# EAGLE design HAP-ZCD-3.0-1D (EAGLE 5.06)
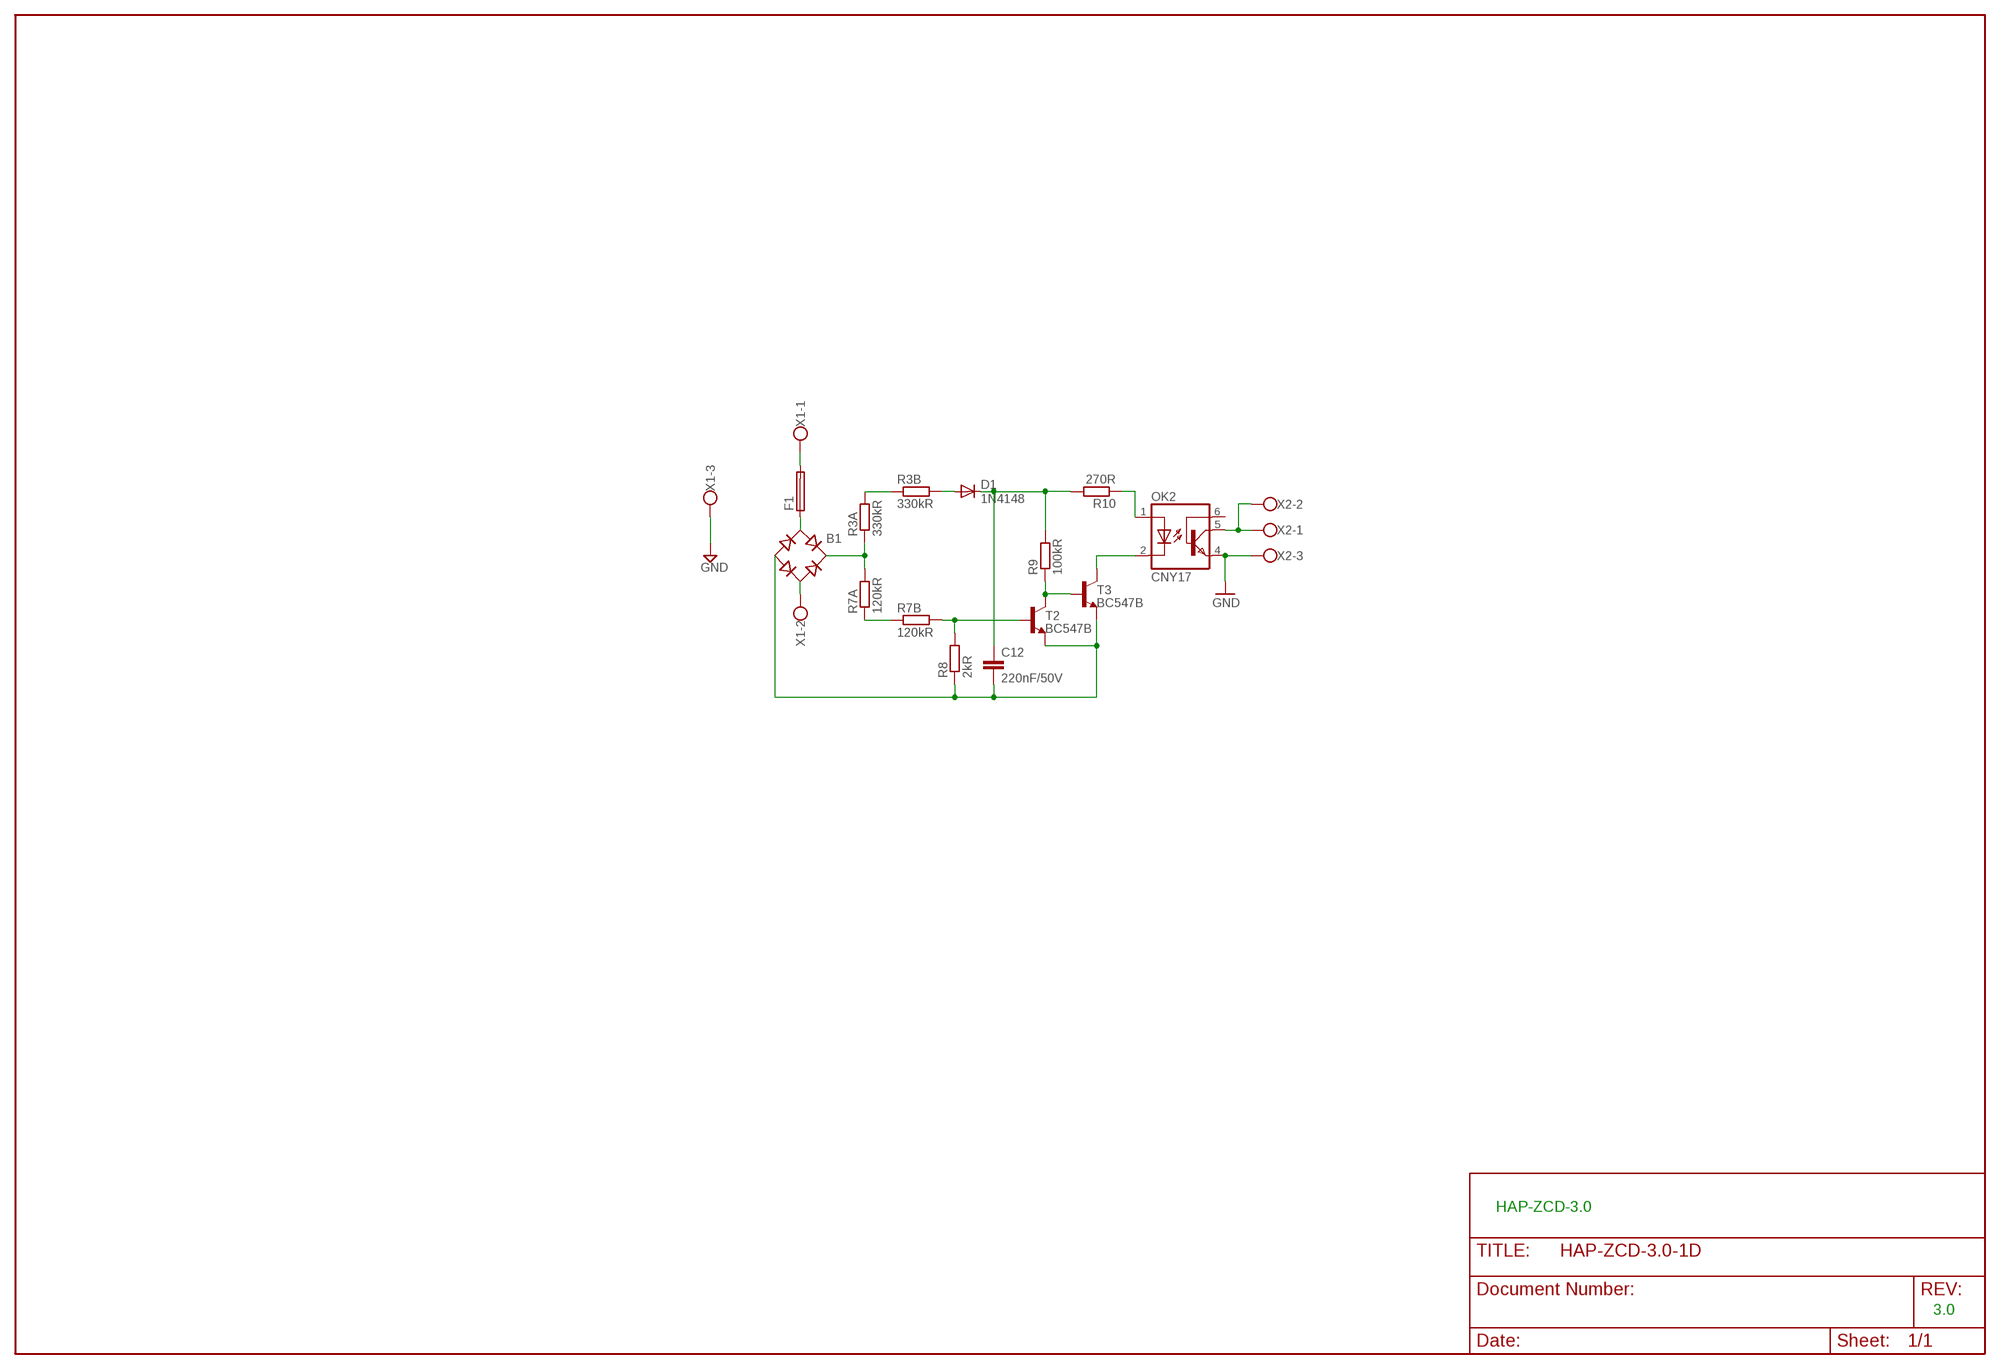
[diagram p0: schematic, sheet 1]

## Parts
B1  B-DIL  [B-DIL]
C12  220nF/50V  C-EU025-025X050  [C025-025X050]
D1  1N4148  [DO35-10]
F1  19560  [19560]
OK2  CNY17  [DIL06]
R3A  330kR  R-EU_0207/2V  [0207/2V]
R3B  330kR  R-EU_0207/2V  [0207/2V]
R7A  120kR  R-EU_0207/2V  [0207/2V]
R7B  120kR  R-EU_0207/2V  [0207/2V]
R8  2kR  R-EU_0207/2V  [0207/2V]
R9  100kR  R-EU_0207/2V  [0207/2V]
R10  270R  R-EU_0207/2V  [0207/2V]
T2  BC547B  [TO92]
T3  BC547B  [TO92]
X1  W237-03P  [W237-133]
X2  W237-03P  [W237-133]

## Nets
GND: OK2.4(EMI) X2.3
GND230: X1.3 ; supply symbol labelled GND
N$1: R9.1 T2.3(C) T3.2(B)
N$2 [mains]: B1.AC2 X1.2
N$3 [mains]: B1.AC1 F1.1
N$4: OK2.1(A) R10.1
N$5: OK2.5(COL) X2.1 X2.2
N$6 [mains]: F1.2 X1.1
N$25: R3A.2 R3B.1
N$26: R7B.2 R8.2 T2.2(B)
N$34: B1.+ R3A.1 R7A.2
N$37: R7A.1 R7B.1
N$38: B1.- C12.2 R8.1 T2.1(E) T3.1(E)
N$40: D1.A R3B.2
N$57: C12.1 D1.C R9.2 R10.2
N$62: OK2.2(C) T3.3(C)
Unconnected: OK2.6(BAS)

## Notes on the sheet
- HAP-ZCD-3.0
- 3.0

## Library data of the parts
B1 = rectifier:B-DIL: RECTIFIER
C12 = rcl:C-EU: CAPACITOR, European symbol
D1 = diode:1N4148: DIODE
F1 = fuse:19560: FUSE HOLDER
OK2 = optocoupler:CNY17: SIEMENS OPTO COUPLER
R3A R3B R7A R7B R8-R10 = rcl:R-EU_: RESISTOR, European symbol
T2 T3 = transistor-npn:BC547*: NPN Transistor
X1 X2 = con-wago-508:W237-03P: WAGO SREW CLAMP

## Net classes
0 default: width 0.406 mm, clearance 0.406 mm
1 mains: width 0.61 mm, clearance 0.61 mm

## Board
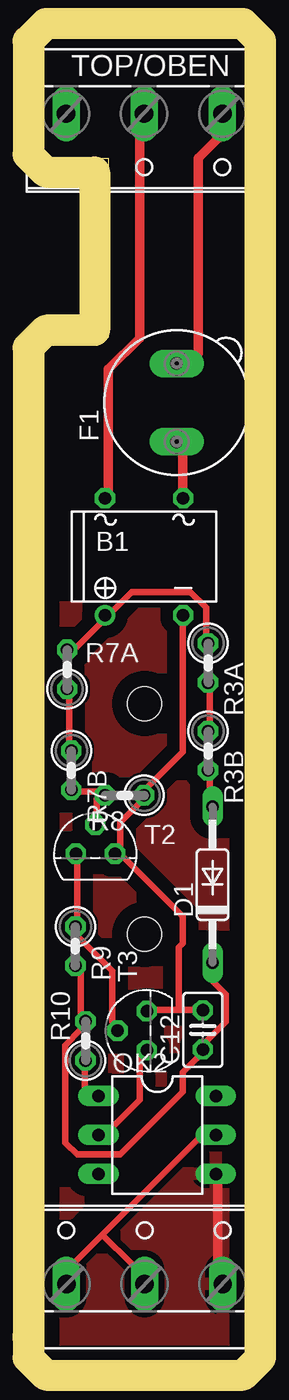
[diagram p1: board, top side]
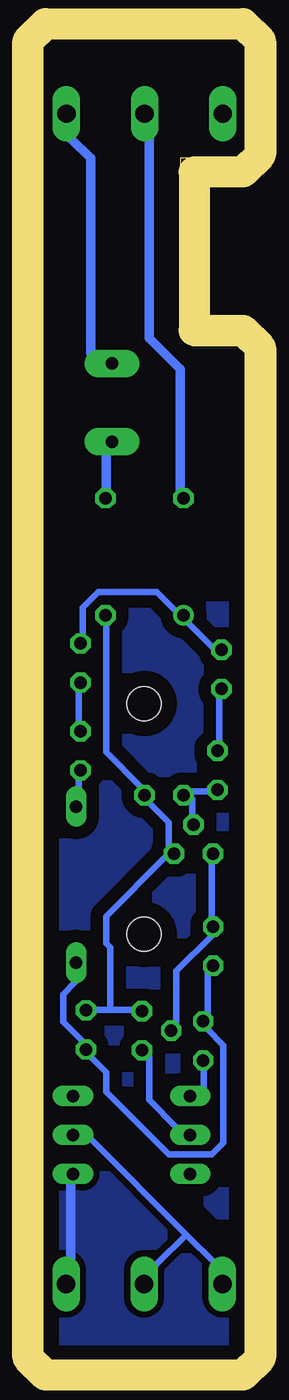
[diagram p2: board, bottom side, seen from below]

Size 13.1 x 86 mm. Coordinates in mm from the lower left corner, seen from the top.
Outline: 0,66.04 0,0 13.1,0 13.1,86 0,86 0,78.2 4.19,78.2 4.19,66.56 3.46,66.04 0,66.04
Copper layers (1*16): Top 0.035mm / dielectric 1.5mm / Bottom 0.035mm
Design rules "default": minimum track width 10mil, minimum drill 24mil, track to track 8mil, track to pad 8mil, pad to pad 8mil, via to via 8mil, smd to smd 8mil, copper to edge 40mil, drill to drill 8mil, minimum pad ring 10mil, minimum via ring 8mil, stop-mask expansion 4mil, vias tented up to drill 0mil, thermal gap 10mil
Holes 2.2 mm at 6.55,42.75 6.55,27.75
Milling: 16 lines

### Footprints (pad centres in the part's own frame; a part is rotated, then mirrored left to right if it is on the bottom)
B-DIL = drill 0.813 round: + -2.54,-3.81 | drill 0.813 octagon: - 2.54,-3.81; AC1 2.54,3.81; AC2 -2.54,3.81
C025-025X050 = drill 0.813 octagon: 1 -1.27,0; 2 1.27,0
DO35-10 = drill 0.813 long: A 5.08,0; C -5.08,0
19560 = drill 0.813 pad 1.778 long: 1 -2.54,0; 2 2.54,0
DIL06 = drill 0.813 long: 1 -2.54,-3.81; 2 0,-3.81; 3 2.54,-3.81; 4 2.54,3.81; 5 0,3.81; 6 -2.54,3.81
0207/2V = drill 0.813 octagon: 1 -1.27,0; 2 1.27,0
TO92 = drill 0.813 octagon: 1 1.27,0; 2 0,1.905; 3 -1.27,0
W237-133 = drill 1.194 long: 1 -5.08,-0.635; 2 0,-0.635; 3 5.08,-0.635

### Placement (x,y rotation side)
B1  6.52,52.3 0 top
C12  10.33,21.54 90 top
D1  10.96,30.98 90 top
F1  8.64,62.33 90 top
OK2  7.36,14.7 270 top
R3A  10.68,45.39 270 top
R3B  10.68,39.67 270 top
R7A  1.51,44.97 90 top
R7B  1.79,38.41 270 top
R8  5.25,36.79 180 top
R9  2.05,26.98 270 top
R10  2.71,20.82 90 top
T2  3.34,32.98 0 top
T3  6.69,21.48 90 top
X1  6.52,80.47 180 top
X2  6.54,5.64 0 top

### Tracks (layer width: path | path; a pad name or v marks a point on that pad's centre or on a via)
GND
  Top 0.61: OK2.4 11.3,11.65 11.3,6.57 X2.3
  pour Top (isolate 0.406): 0.38,7.08 2.92,7.08 10.54,14.7 13.08,14.7 13.08,-0.54 0.38,-0.54
GND1
  Bottom 0.61: 11.18,12.16 11.3,11.65 11.3,6.57 11.62,5.01
  pour Bottom (isolate 0.406): 0.38,7.08 2.92,7.08 10.54,14.7 13.08,14.7 13.08,-0.54 0.38,-0.54
GND2
  pour Bottom (isolate 0.813): 0.38,48.99 13.08,48.99 13.08,19.78 11.81,18.51 10.54,18.51 1.65,9.62 0.38,9.62 -0.25,10.26
GND230
  pour Top (isolate 0.813): 0.38,48.99 13.08,48.99 13.08,19.78 11.81,18.51 10.54,18.51 1.65,9.62 0.38,9.62 -0.25,10.26
N$1
  Top 0.406: T3.2 4.44,22.07 4.44,25.37 2.16,27.65 R9.1 2.16,28.67 2.16,32.48 T2.3
N$2
  Top 0.61: B1.AC2 4.19,56.61 4.19,64.48 6.22,66.52 6.22,79.47 X1.2
N$3
  Top 0.61: B1.AC1 9.02,56.61 9.02,59.15 F1.1
N$4
  Top 0.406: R10.1 2.67,19.02 2.67,17.75 OK2.1
N$5
  Top 0.406: 3.81,8.22 1.9,6.32 X2.1 | 3.81,8.22 10.03,14.45 OK2.5 | X2.2 5.71,6.32 3.81,8.22
N$6
  Top 0.61: F1.2 10.03,65.5 10.03,78.2 11.3,79.47 X1.1
N$7
  Bottom 0.406: 1.79,39.67 1.65,40.1 1.65,43.15 1.51,43.7
N$8
  Bottom 0.406: 8.76,22.83 9.78,22.83 10.33,22.8 | 8.76,22.83 7.24,22.83 6.69,22.75 | 9.06,48.49 9.02,47.97 9.02,39.59 6.73,37.31 6.52,36.79 6.22,36.29 4.95,35.02 4.95,33.5 4.61,32.98 5.21,32.73 9.02,28.92 9.02,27.15 8.76,26.89 8.76,22.83
N$9
  Bottom 0.406: 10.96,36.06 10.79,37.31 10.79,37.81 10.68,38.41
N$10
  Bottom 0.406: 2.05,25.7 2.41,25.37 2.41,22.57 2.71,22.09 2.41,21.56 1.4,20.54 1.4,14.19 2.16,13.43 4.95,13.43 9.02,17.49 9.02,18.76 10.03,19.78 10.33,20.27 10.54,20.8 11.81,22.07 11.81,23.84 11.05,24.61 10.96,25.9
N$11
  Bottom 0.406: 3.56,14.7 4.44,15.21 6.22,16.99 6.22,19.78 6.69,20.2
N$12
  Bottom 0.406: 10.68,40.95 10.79,41.37 10.79,43.66 10.68,44.12
N$13
  Bottom 0.406: 3.34,34.88 3.43,35.53 3.43,36.54 3.98,36.79 3.43,37.05 2.41,37.05 1.79,37.13
N$14
  Bottom 0.406: 1.51,46.24 2.16,46.45 3.68,47.97 3.98,48.49 4.44,48.74 5.71,50.01 9.52,50.01 10.54,48.99 10.54,47.21 10.68,46.66
N$15
  Bottom 0.406: 4.78,21.48 4.44,22.07 4.44,25.37 2.16,27.65 2.05,28.25 2.16,28.67 2.16,32.48 2.08,32.98
N$16
  Bottom 0.61: 9.06,56.11 9.02,56.61 9.02,59.15 8.64,59.78
N$17
  Bottom 0.406: 2.71,19.55 2.67,19.02 2.67,17.75 3.56,17.24
N$18
  Bottom 0.406: 3.81,8.22 1.9,6.32 1.46,5.01 | 3.81,8.22 10.03,14.45 11.18,14.7 | 6.54,5.01 5.71,6.32 3.81,8.22
N$19
  Bottom 0.61: 3.98,56.11 4.19,56.61 4.19,64.48 6.22,66.52 6.22,79.47 6.52,81.11
N$20
  Bottom 0.61: 8.64,64.87 10.03,65.5 10.03,78.2 11.3,79.47 11.6,81.11
N$25
  Top 0.406: R3B.1 10.79,41.37 10.79,43.66 R3A.2
N$26
  Top 0.406: T2.2 3.43,35.53 3.43,36.54 R8.2 3.43,37.05 2.41,37.05 R7B.2
N$34
  Top 0.406: R7A.2 2.16,46.45 3.68,47.97 B1.+ 4.44,48.74 5.71,50.01 9.52,50.01 10.54,48.99 10.54,47.21 R3A.1
N$37
  Top 0.406: R7B.1 1.65,40.1 1.65,43.15 R7A.1
N$38
  Top 0.406: 8.76,22.83 9.78,22.83 C12.2 | 8.76,22.83 7.24,22.83 T3.1 | B1.- 9.02,47.97 9.02,39.59 6.73,37.31 R8.1 6.22,36.29 4.95,35.02 4.95,33.5 T2.1 5.21,32.73 9.02,28.92 9.02,27.15 8.76,26.89 8.76,22.83
N$40
  Top 0.406: D1.A 10.79,37.31 10.79,37.81 R3B.2
N$57
  Top 0.406: R9.2 2.41,25.37 2.41,22.57 R10.2 2.41,21.56 1.4,20.54 1.4,14.19 2.16,13.43 4.95,13.43 9.02,17.49 9.02,18.76 10.03,19.78 C12.1 10.54,20.8 11.81,22.07 11.81,23.84 11.05,24.61 D1.C
N$62
  Top 0.406: OK2.2 4.44,15.21 6.22,16.99 6.22,19.78 T3.3

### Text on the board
tPlace: TOP/OBEN
tStop: TOP/OBEN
